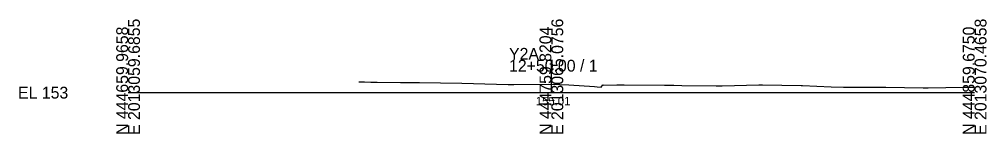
# Model space of a CAD drawing. Extents: x -26 to 203, y -10 to 5517.
# Drawn here: x -25.7 to 202.8, y 4990.3 to 5017.3 of the extents above; entities that cross this region are included whole.
import ezdxf

# ---------------------------------------------------------------- set-up
doc = ezdxf.new("R2010")
doc.units = 0
for name, color, linetype in [('Default', 7, 'Continuous'), ('Exist Cross Section Cell', 7, 'Continuous'), ('Exist XS Center Line Elevation Label', 7, 'Continuous'), ('Exist XS Ground Line', 7, 'Continuous')]:
    doc.layers.add(name, color=color, linetype=linetype)

msp = doc.modelspace()

# ---------------------------------------------------------------- linework, layer by layer
at = {"layer": 'Exist Cross Section Cell'}
for p, q in [((100, 5000), (100, 5007.77)), ((0, 5000), (100, 5000)), ((100, 5000), (200, 5000))]:
    msp.add_line(p, q, dxfattribs=at)
at = {"layer": 'Exist XS Ground Line'}
msp.add_lwpolyline([(54.53, 5002.59), (55.06, 5002.53), (55.88, 5002.59), (57.34, 5002.48), (58.84, 5002.45), (64.33, 5002.36), (68.85, 5002.37), (73.83, 5002.32), (78.87, 5002.21), (87.05, 5001.99), (89.78, 5001.93), (91.16, 5001.94), (99.95, 5002.02), (104.1, 5001.81), (110.17, 5001.43), (110.81, 5001.39), (111.76, 5001.33), (112.17, 5001.83), (112.27, 5001.73), (115.5, 5001.81), (117.18, 5001.81), (126.72, 5001.74), (128.95, 5001.77), (130.85, 5001.7), (138.96, 5001.58), (140.35, 5001.59), (148.98, 5001.87), (149.86, 5001.85), (159, 5001.68), (159.36, 5001.68), (166.07, 5001.4), (169.01, 5001.28), (178.36, 5001.28), (179.03, 5001.26), (187.87, 5001.14), (189.04, 5001.13), (197.37, 5001.29), (199.06, 5001.28), (200, 5001.27)], dxfattribs=at)

# ---------------------------------------------------------------- texts
at = {"layer": 'Default'}
msp.add_text('-', height=0.0001, dxfattribs=at).set_placement((0, 5000))
at = {"layer": 'Exist Cross Section Cell'}
for s, p in [('E 2013059.6855', (2.8, 4990)), ('E 2013065.0756', (102.8, 4990)), ('E 2013070.4658', (202.8, 4990)), ('N 444659.9658', (0, 4990)), ('N 444759.8204', (100, 4990)), ('N 444859.6750', (200, 4990))]:
    msp.add_text(s, height=2.8, rotation=90, dxfattribs=at).set_placement(p)
for s, p in [('Y2A', (90, 5007.77)), ('12+50.00 / 1', (90, 5004.97)), ('EL 153', (-26, 4998.6))]:
    msp.add_text(s, height=2.8, dxfattribs=at).set_placement(p)
at = {"layer": 'Exist XS Center Line Elevation Label'}
msp.add_text('155.01', height=2, dxfattribs=at).set_placement((96.32, 4997.01))

doc.saveas('drawing.dxf')
